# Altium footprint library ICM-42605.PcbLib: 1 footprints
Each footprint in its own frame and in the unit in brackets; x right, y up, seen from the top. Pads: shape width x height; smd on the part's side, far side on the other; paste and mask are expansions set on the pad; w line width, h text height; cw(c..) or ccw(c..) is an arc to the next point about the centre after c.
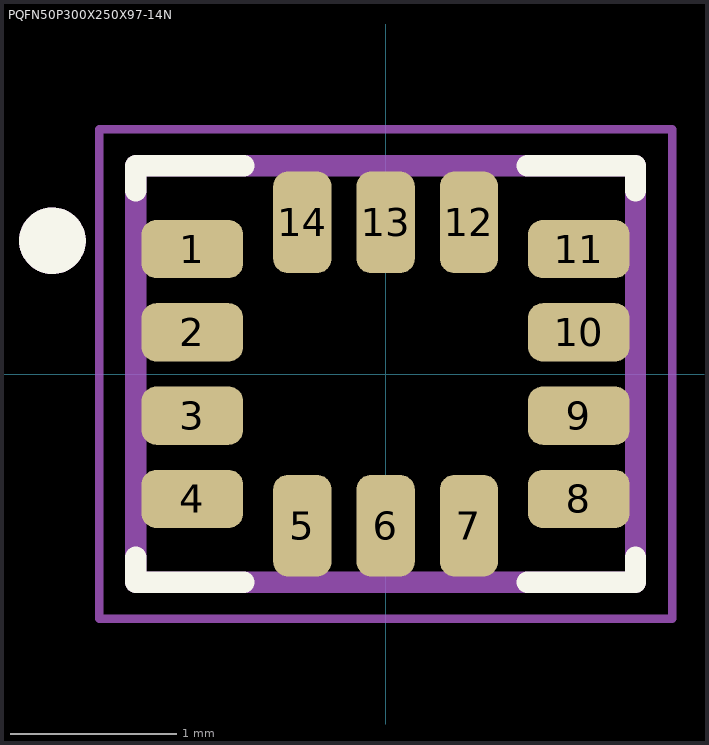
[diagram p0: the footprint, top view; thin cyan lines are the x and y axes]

## PQFN50P300X250X97-14N [mm]
pads (14):
  rrect50% 0.61x0.35 smd: 1(-1.16,0.75) 2(-1.16,0.25) 3(-1.16,-0.25) 4(-1.16,-0.75) 8(1.16,-0.75) 9(1.16,-0.25) 10(1.16,0.25) 11(1.16,0.75)
  rrect50% 0.35x0.61 smd: 5(-0.5,-0.91) 6(0,-0.91) 7(0.5,-0.91) 12(0.5,0.91) 13(0,0.91) 14(-0.5,0.91)
Top Overlay:
  circle w0.2: c-2,0.8 r0.1
  lines w0.127: -1.5,-1.1 -1.5,-1.25 -0.85,-1.25 ; -1.5,1.1 -1.5,1.25 -0.85,1.25 ; 0.85,-1.25 1.5,-1.25 1.5,-1.1 ; 0.85,1.25 1.5,1.25 1.5,1.1
Mechanical 13:
  circle w0.2: c-2,0.8 r0.1
  lines w0.127: -1.5,-1.25 1.5,-1.25 1.5,1.25 -1.5,1.25 -1.5,-1.25
Mechanical 15:
  lines w0.05: -1.72,-1.47 1.72,-1.47 1.72,1.47 -1.72,1.47 -1.72,-1.47
3D body "ICM-42605--3DModel-STEP-1.STEP": height 0.96, standoff -0.01, extent -1.5,-1.25 1.5,1.25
